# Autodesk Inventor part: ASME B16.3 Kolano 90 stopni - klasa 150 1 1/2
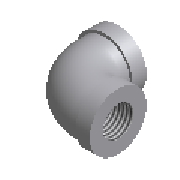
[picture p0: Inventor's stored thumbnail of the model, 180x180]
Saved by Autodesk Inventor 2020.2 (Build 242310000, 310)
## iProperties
Manager: www.cadconsulting.pl
Company: Fabian Stasiak CAD Consulting
NAME: PIPING: ASME B16.3 90 Deg Elbow - Class 150
DATA: <meta><inlinegroups number="0" deflen="0"></inlinegroups><connections number="2"></connections><angles><a>1.57079632679489</a></angles></meta>
IsCustomPart: 0
Created: 2014-02
Part Number: ASME B16.3 Kolano 90 stopni - klasa 150 1 1/2
Material: Żelazo, ciągliwe
Description: Kolano
Document SubType Name: Modeling
Standard: ASME B16.3
Designer: F.Stasiak
Standard Revision: 1988
Standards Organization: ANSI
Language: pl-PL
Size Designation: 1 1/2
Categories: <MemberInstance><Categories><Category DisplayName="Rury cienko- i grubościenne" InternalName="4347fa0f-2144-441d-94cd-e3e15c92b736" Mnemonic="TUBEANDPIPE"><Cate
Density: 7.15 g/cm^3
Appearance: Częściowo polerowana
Catalog Web Link: www.expertbooks.pl
Author: F.Stasiak
Subject: Zbiór ćwiczeń. Autodesk Inventor 2020. Kurs Professional
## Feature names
1. Revolution1
2. Sweep1
3. Revolution2
## Parameters: MD = 44.52036 mm, A = 49.276 mm, B = 17.78 mm, G = 3.81 mm, F1 = 50.038 mm, d0 = 44.52036 mm, d1 = 57.658 mm, d2 = 61.722 mm, d3 = 9.398 mm, d4 = 17.78 mm, d5 = 0.3124 mm, d16 = 90 deg, d6 = 50.038 mm, d7 = 57.658 mm, d8 = 90 deg, d9 = 49.276 mm, d10 = 31.496 mm, d11 = 0, d12 = 0.3124 mm, d13 = 17.78 mm, d14 = 9.398 mm, d15 = 44.52036 mm, d17 = 57.658 mm, d18 = 61.722 mm, d51 = 90 deg, P = 2.20871 mm, d58 = 17.78 mm, d59 = 0, d60 = 25.4 mm, d61 = 0, H = 61.722 mm, E1 = 9.398 mm, d63 = 0, Size_Designation = 15 mm
